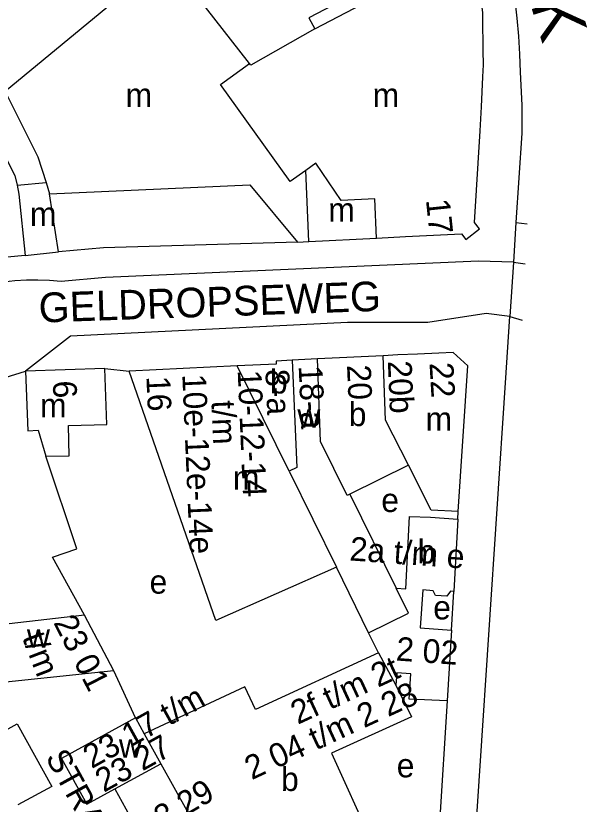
# Model space of a CAD drawing. Extents: x 160673 to 161924, y 382258 to 384145.
# Drawn here: x 161785.9 to 161882.1, y 382756.1 to 382888.8 of the extents above; entities that cross this region are included whole.
import ezdxf

# ---------------------------------------------------------------- set-up
doc = ezdxf.new("R2010")
doc.units = 0
for name, color, linetype in [('BLT_Basislijn', 7, 'Continuous'), ('BLT_Bebouwing', 7, 'Continuous'), ('BLT_Centroide', 7, 'Continuous'), ('BLT_Huisnummer', 7, 'Continuous'), ('BLT_Huisnummer_reeks', 7, 'Continuous'), ('BLT_Onderdoorgang_en_onderverdeling', 7, 'Continuous'), ('BLT_Onderverdeling_panden', 7, 'Continuous'), ('BLT_Straatnaam', 7, 'Continuous'), ('BLT_Straatnaam_hoofdweg', 7, 'Continuous'), ('BLT_Straatnaam_verkleind', 7, 'Continuous'), ('BLT_Vlakafsluiter', 7, 'Continuous')]:
    doc.layers.add(name, color=color, linetype=linetype)

msp = doc.modelspace()

# ---------------------------------------------------------------- linework, layer by layer
at = {"layer": 'BLT_Basislijn'}
for p, q in [((161871.06, 382869.05), (161870.09, 382854.01)), ((161870.09, 382854.01), (161869.67, 382847.3)), ((161800.93, 382829.41), (161805.05, 382829)), ((161860.31, 382804.08), (161860.37, 382805.35)), ((161859.25, 382785.39), (161859.63, 382791.89)), ((161806.07, 382770.64), (161802.43, 382778.58)), ((161858.54, 382773.49), (161856.96, 382748.72))]:
    msp.add_line(p, q, dxfattribs=at)
for points in [[(161869.01, 382897.4), (161869.51, 382894.41), (161869.93, 382891.41), (161870.27, 382888.39), (161870.53, 382885.37), (161870.72, 382882.34), (161870.82, 382879.31), (161871.09, 382873.74), (161871.06, 382869.05)], [(161833.32, 382850.71), (161800.73, 382849.75), (161793.13, 382849.08)], [(161869.67, 382847.3), (161863.78, 382847.48), (161801.03, 382844.75), (161793.56, 382844.1)], [(161793.56, 382844.1), (161791.63, 382844.24), (161789.68, 382844.29), (161787.74, 382844.27), (161785.8, 382844.16), (161783.87, 382843.98), (161781.95, 382843.71), (161780.04, 382843.37), (161778.14, 382842.95), (161776.26, 382842.45), (161774.41, 382841.88), (161772.58, 382841.22), (161771.86, 382840.94)], [(161869.09, 382838.2), (161865.11, 382838.66), (161855.27, 382837.15), (161841.77, 382837.16), (161795.13, 382834.86), (161787.59, 382828.98)], [(161807.31, 382603.5), (161808.62, 382604.01), (161826.42, 382610.98), (161835.69, 382614.61), (161837.55, 382615.63), (161838.9, 382616.97), (161839.97, 382618.7), (161840.6, 382620.41), (161843.11, 382631.15), (161847.83, 382651.39), (161852.26, 382670.37), (161854.47, 382680.15), (161857.74, 382697.6), (161859.63, 382710.05), (161860.56, 382717.51), (161862.36, 382736.25), (161864.15, 382763.42), (161868.36, 382827), (161869.09, 382838.2)], [(161773.44, 382824.94), (161773.84, 382824.74), (161787.59, 382828.98)], [(161797.5, 382787.92), (161792.11, 382797.67), (161796.2, 382799.07), (161790.98, 382814.66)]]:
    msp.add_lwpolyline(points, dxfattribs=at)
at = {"layer": 'BLT_Bebouwing'}
for p, q in [((161809.67, 382897.12), (161784.14, 382876.02)), ((161864.6, 382882.94), (161864.55, 382888.45)), ((161864.28, 382873.46), (161864.52, 382878.52)), ((161864.08, 382869.43), (161864.28, 382873.46)), ((161786.16, 382860.28), (161791.04, 382860.71)), ((161791.04, 382860.71), (161791.64, 382858.81)), ((161793.13, 382849.08), (161791.64, 382858.81)), ((161833.32, 382850.71), (161835.28, 382850.8)), ((161835.28, 382850.8), (161846.62, 382851.38)), ((161787.52, 382848.44), (161793.13, 382849.08)), ((161787.52, 382848.44), (161784.52, 382848.14)), ((161850.21, 382831.71), (161847.76, 382831.57)), ((161853.53, 382831.86), (161850.21, 382831.71)), ((161836.69, 382831.07), (161832.46, 382830.81)), ((161847.76, 382831.57), (161836.69, 382831.07)), ((161823.17, 382829.86), (161805.05, 382829)), ((161852.01, 382813.15), (161842.13, 382808.29)), ((161842.13, 382808.29), (161849.93, 382792.45)), ((161860.31, 382804.08), (161859.63, 382791.89)), ((161859.25, 382785.39), (161858.54, 382773.49)), ((161806.07, 382770.64), (161807.57, 382767.94))]:
    msp.add_line(p, q, dxfattribs=at)
for points in [[(161862.22, 382902.58), (161857.3, 382900), (161835.28, 382888.43), (161836.24, 382886.59)], [(161836.24, 382886.59), (161858.62, 382898.34), (161861.77, 382900), (161863.03, 382900.65)], [(161864.55, 382888.45), (161864.54, 382889.35), (161863.77, 382895.2)], [(161864.52, 382878.52), (161864.62, 382880.51), (161864.6, 382882.94)], [(161784.14, 382876.02), (161789.67, 382865.07), (161791.04, 382860.71)], [(161781.64, 382869.92), (161785.8, 382861.92), (161786.16, 382860.28)], [(161846.62, 382851.38), (161851.49, 382851.64), (161860.94, 382852.07), (161861.67, 382851.15), (161863.95, 382852.93), (161863.11, 382853.99), (161864.08, 382869.43)], [(161791.64, 382858.81), (161825.32, 382860.35), (161833.32, 382850.71)], [(161862.02, 382829.88), (161859.55, 382832.14), (161857.14, 382832.02), (161853.53, 382831.86)], [(161832.46, 382830.81), (161829.74, 382830.68), (161829.77, 382830.17), (161823.17, 382829.86)], [(161800.93, 382829.41), (161787.59, 382828.98)], [(161794.96, 382814.76), (161794.8, 382819.84), (161801.26, 382820.03), (161800.93, 382829.41)], [(161839.91, 382795.98), (161819.58, 382787.01), (161805.05, 382829)], [(161860.37, 382805.35), (161862.02, 382829.88)], [(161787.59, 382828.98), (161787.98, 382818.96), (161789.7, 382819.03), (161790.98, 382814.66)], [(161790.98, 382814.66), (161794.96, 382814.76)], [(161860.37, 382805.35), (161855.82, 382805.58), (161852.01, 382813.15)], [(161851.6, 382792.38), (161852.2, 382804.53), (161855.75, 382804.39), (161860.31, 382804.08)], [(161845.31, 382784.95), (161839.91, 382795.98)], [(161849.93, 382792.45), (161851.6, 382792.38)], [(161854.42, 382792.21), (161853.96, 382785.77), (161859.25, 382785.39)], [(161859.63, 382791.89), (161859.07, 382791.95), (161858.49, 382791.1), (161856.56, 382791.24), (161856.17, 382792.04), (161854.42, 382792.21)], [(161797.5, 382787.92), (161784.86, 382786.47)], [(161802.43, 382778.58), (161797.5, 382787.92)], [(161846.95, 382781.6), (161845.31, 382784.95)], [(161846.95, 382781.6), (161826.29, 382772.04), (161824.51, 382775.86), (161807.57, 382767.94)], [(161802.43, 382778.58), (161778.92, 382776.11)], [(161858.54, 382773.49), (161852.12, 382773.81), (161852.44, 382778.06), (161850.04, 382778.23), (161849.89, 382776.16)], [(161849.89, 382776.16), (161852.53, 382770.82), (161839.05, 382764.7)], [(161806.07, 382770.64), (161793.67, 382763.82), (161797.9, 382756.12), (161802.61, 382758.69)], [(161782.19, 382767.44), (161786.19, 382769.61), (161792, 382759.11), (161786.31, 382755.99)], [(161839.05, 382764.7), (161845.72, 382749.99), (161845.9, 382749.6)], [(161802.61, 382758.69), (161814.33, 382737.41), (161822.14, 382741.72)]]:
    msp.add_lwpolyline(points, dxfattribs=at)
at = {"layer": 'BLT_Onderdoorgang_en_onderverdeling'}
msp.add_lwpolyline([(161786.16, 382860.28), (161786.49, 382858.76), (161787.52, 382848.44)], dxfattribs=at)
at = {"layer": 'BLT_Onderverdeling_panden'}
for p, q in [((161835.28, 382850.8), (161834.77, 382862.77)), ((161848.17, 382820.76), (161847.76, 382831.57)), ((161831.93, 382812.13), (161823.17, 382829.86)), ((161852.01, 382813.15), (161848.17, 382820.76)), ((161831.93, 382812.13), (161839.91, 382795.98)), ((161846.95, 382781.6), (161849.89, 382776.16)), ((161802.61, 382758.69), (161810.36, 382762.92))]:
    msp.add_line(p, q, dxfattribs=at)
for points in [[(161825.26, 382880.78), (161816.48, 382892.08), (161814.47, 382891.32), (161809.67, 382897.12)], [(161836.24, 382886.59), (161825.5, 382880.48), (161825.26, 382880.78)], [(161834.77, 382862.77), (161832.14, 382860.88), (161820.39, 382877.25), (161825.26, 382880.78)], [(161846.62, 382851.38), (161846.33, 382857.96), (161840.69, 382857.72), (161836.43, 382864.01), (161834.77, 382862.77)], [(161832.46, 382830.81), (161833.23, 382812.79), (161831.93, 382812.13)], [(161842.13, 382808.29), (161841.7, 382808.08), (161837.24, 382817.14), (161836.69, 382831.07)], [(161845.31, 382784.95), (161852, 382788.25), (161849.93, 382792.45)], [(161807.57, 382767.94), (161810.36, 382762.92)], [(161810.36, 382762.92), (161814.74, 382755.03)]]:
    msp.add_lwpolyline(points, dxfattribs=at)
at = {"layer": 'BLT_Vlakafsluiter'}
for p, q in [((161870.09, 382854.01), (161872.01, 382853.78)), ((161869.67, 382847.3), (161869.09, 382838.2)), ((161869.67, 382847.3), (161871.64, 382847.05)), ((161869.09, 382838.2), (161871.13, 382837.57))]:
    msp.add_line(p, q, dxfattribs=at)

# ---------------------------------------------------------------- texts
at = {"layer": 'BLT_Centroide'}
for s, p in [('m', (161804.43, 382873.45)), ('m', (161845.99, 382873.45)), ('m', (161838.53, 382854.16)), ('m', (161788.33, 382853.44)), ('b', (161828.71, 382825.23)), ('m', (161790.03, 382821.24)), ('b', (161841.97, 382819.75)), ('w', (161833.33, 382819.49)), ('m', (161854.89, 382818.95)), ('m', (161822.48, 382809.05)), ('e', (161847.44, 382805.28)), ('b', (161853.56, 382796.63)), ('e', (161808.46, 382791.54)), ('e', (161856.18, 382787.21)), ('w', (161787.83, 382782.44)), ('w', (161803.31, 382763.94)), ('e', (161850.04, 382760.63)), ('b', (161830.58, 382758.34))]:
    msp.add_text(s, height=4, dxfattribs=at).set_placement(p)
at = {"layer": 'BLT_Huisnummer'}
for s, rotation, p in [('17', 275.9228, (161854.95, 382857.81)), ('20', 272.431, (161841.67, 382830)), ('6', 272.0297, (161792.18, 382827.34))]:
    msp.add_text(s, height=4, rotation=rotation, dxfattribs=at).set_placement(p)
at = {"layer": 'BLT_Huisnummer_reeks'}
for s, rotation, p in [('20b', 272.431, (161848.54, 382830.69)), ('8-a', 272.431, (161827.94, 382829.26)), ('18-a', 272.431, (161833.54, 382829.87)), ('22', 273.2997, (161855.55, 382830.36)), ('16', 272.431, (161807.92, 382828.09)), ('10e-12e-14e', 272.431, (161813.96, 382828.43)), ('10-12-14', 272.431, (161823.28, 382829.12)), ('t/m', 272.431, (161818.87, 382823.98)), ('2a t/m e', 355.9028, (161842.03, 382797.14)), ('23 01', 297.1644, (161792.21, 382786.69)), ('t/m', 291.0513, (161786.97, 382784.18)), ('2 02', 355.9028, (161849.83, 382780.3)), ('2f t/m 2t', 24.824, (161833.39, 382769.46)), ('2 04 t/m 2 28', 24.824, (161825.64, 382760.14)), ('23 17 t/m', 29.0591, (161798.71, 382762.01)), ('23 27', 29.0591, (161800.76, 382758.01)), ('23 29', 30.549, (161808.16, 382750.3))]:
    msp.add_text(s, height=4, rotation=rotation, dxfattribs=at).set_placement(p)
at = {"layer": 'BLT_Straatnaam'}
msp.add_text('GELDROPSEWEG', height=5, rotation=1.9765, dxfattribs=at).set_placement((161789.89, 382837.15))
at = {"layer": 'BLT_Straatnaam_hoofdweg'}
msp.add_text('VESTDIJK', height=8, rotation=286.9865, dxfattribs=at).set_placement((161859.66, 382932.82))
at = {"layer": 'BLT_Straatnaam_verkleind'}
msp.add_text('STRATUMSEDIJK', height=4, rotation=298.7634, dxfattribs=at).set_placement((161790.87, 382763.99))

doc.saveas('drawing.dxf')
